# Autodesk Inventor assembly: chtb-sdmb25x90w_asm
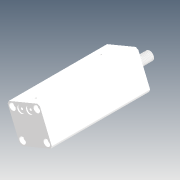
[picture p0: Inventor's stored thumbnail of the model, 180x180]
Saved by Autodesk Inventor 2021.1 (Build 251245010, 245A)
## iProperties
Company: Microsoft
Created: 2018-05
Part Number: chtb-sdmb25x90w_asm
Description: STEP AP214
Document SubType Name: Assembly
Designer: user
Title: chtb-sdmb25x90w_asm.STEP
Author: Windows
Revision Number: ÈÎºÎ
Sending System: SolidWorks 2015
Preprocessor: SwSTEP 2.0
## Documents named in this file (4)
- D:\Vault_2016\Projekty\Clamptek\Hydraulic\CHTB\CHTB-25\Inventor\chtb-sdmb25x90w\chtb-sdmb25x90w_asm.iam
- D:\Vault_2016\Projekty\Clamptek\Hydraulic\CHTB\CHTB-25\Inventor\chtb-sdmb25x90w\CHTB-25QG.ipt
- D:\Vault_2016\Projekty\Clamptek\Hydraulic\CHTB\CHTB-25\Inventor\chtb-sdmb25x90w\CHTB-SDMB25X90NBT.ipt
- D:\Vault_2016\Projekty\Clamptek\Hydraulic\CHTB\CHTB-25\Inventor\chtb-sdmb25x90w\CHTB-SDMB25X90WHSG.ipt
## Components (3 placed, 3 different names)
1. CHTB-25QG_1
2. CHTB-SDMB25X90NBT_2
3. CHTB-SDMB25X90WHSG_3
